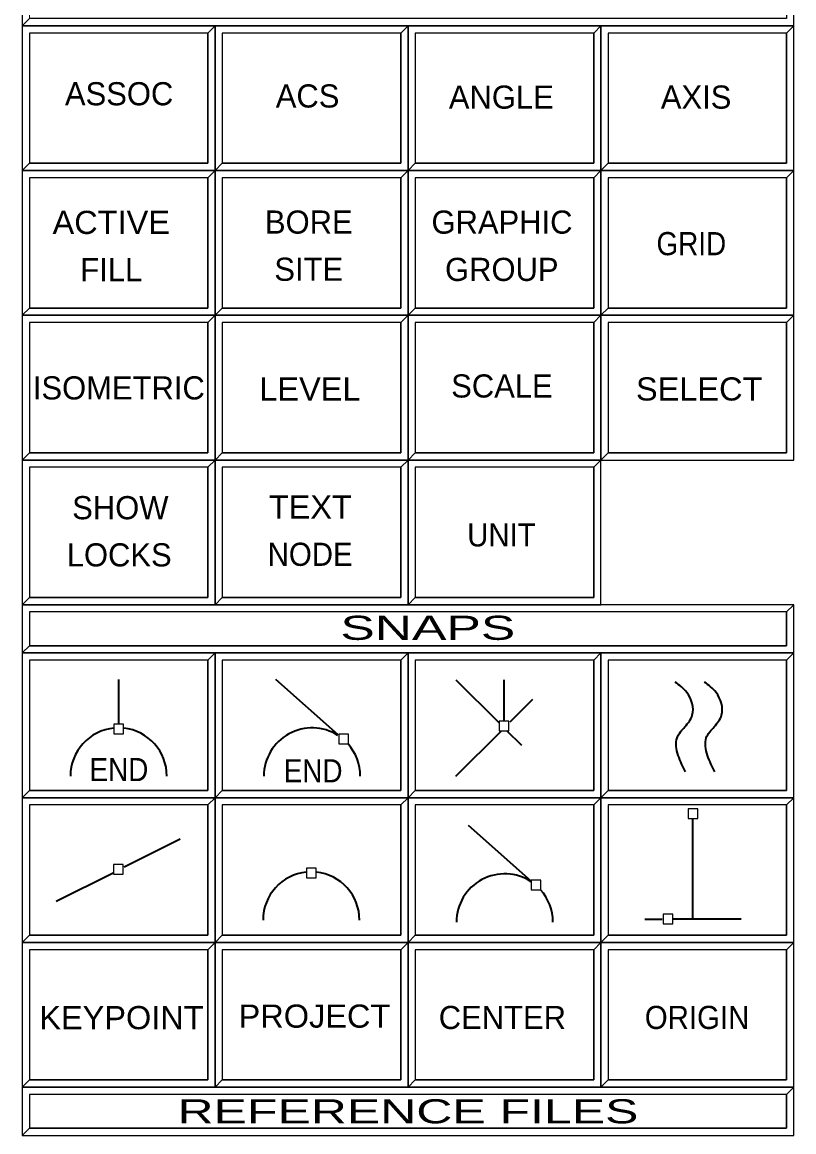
# Model space of a CAD drawing. Extents: x 95906.8 to 95923.6, y 90964.8 to 90972.8.
# Drawn here: x 95916.332 to 95917.932, y 90967.969 to 90970.269 of the extents above; entities that cross this region are included whole.
import ezdxf
from ezdxf.enums import TextEntityAlignment as Align

# ---------------------------------------------------------------- set-up
doc = ezdxf.new("R2010")
doc.units = 0
doc.header["$LTSCALE"] = 0.019
doc.linetypes.add('MEDIUM_DASHED', pattern=[4.5, 3, -1.5])
for name, color, linetype, lineweight in [('1', 7, 'Continuous', 25), ('11', 7, 'Continuous', 25), ('12', 7, 'Continuous', 25), ('2', 7, 'Continuous', 13), ('21', 7, 'Continuous', 25), ('3', 7, 'Continuous', 25), ('6', 7, 'Continuous', 35), ('7', 7, 'Continuous', 35)]:
    doc.layers.add(name, color=color, linetype=linetype, lineweight=lineweight)

msp = doc.modelspace()

# ---------------------------------------------------------------- linework, layer by layer
at = {"layer": '1'}
for points in [[(95916.3323, 90970.2617), (95917.9323, 90970.2617), (95917.9323, 90970.3617), (95916.3323, 90970.3617)], [(95916.3323, 90969.9617), (95916.7323, 90969.9617), (95916.7323, 90970.2617), (95916.3323, 90970.2617)], [(95916.7323, 90969.9617), (95917.1323, 90969.9617), (95917.1323, 90970.2617), (95916.7323, 90970.2617)], [(95917.1323, 90969.9617), (95917.5323, 90969.9617), (95917.5323, 90970.2617), (95917.1323, 90970.2617)], [(95917.5323, 90969.9617), (95917.9323, 90969.9617), (95917.9323, 90970.2617), (95917.5323, 90970.2617)], [(95916.3323, 90969.6617), (95916.7323, 90969.6617), (95916.7323, 90969.9617), (95916.3323, 90969.9617)], [(95916.7323, 90969.6617), (95917.1323, 90969.6617), (95917.1323, 90969.9617), (95916.7323, 90969.9617)], [(95917.1323, 90969.6617), (95917.5323, 90969.6617), (95917.5323, 90969.9617), (95917.1323, 90969.9617)], [(95917.5323, 90969.6617), (95917.9323, 90969.6617), (95917.9323, 90969.9617), (95917.5323, 90969.9617)], [(95916.3323, 90969.3617), (95916.7323, 90969.3617), (95916.7323, 90969.6617), (95916.3323, 90969.6617)], [(95916.7323, 90969.3617), (95917.1323, 90969.3617), (95917.1323, 90969.6617), (95916.7323, 90969.6617)], [(95917.1323, 90969.3617), (95917.5323, 90969.3617), (95917.5323, 90969.6617), (95917.1323, 90969.6617)], [(95917.5323, 90969.3617), (95917.9323, 90969.3617), (95917.9323, 90969.6617), (95917.5323, 90969.6617)], [(95916.3323, 90969.0617), (95916.7323, 90969.0617), (95916.7323, 90969.3617), (95916.3323, 90969.3617)], [(95916.7323, 90969.0617), (95917.1323, 90969.0617), (95917.1323, 90969.3617), (95916.7323, 90969.3617)], [(95917.1323, 90969.0617), (95917.5323, 90969.0617), (95917.5323, 90969.3617), (95917.1323, 90969.3617)], [(95916.3323, 90968.9617), (95917.9323, 90968.9617), (95917.9323, 90969.0617), (95916.3323, 90969.0617)], [(95916.3323, 90968.6617), (95916.7323, 90968.6617), (95916.7323, 90968.9617), (95916.3323, 90968.9617)], [(95916.7323, 90968.6617), (95917.1323, 90968.6617), (95917.1323, 90968.9617), (95916.7323, 90968.9617)], [(95917.1323, 90968.6617), (95917.5323, 90968.6617), (95917.5323, 90968.9617), (95917.1323, 90968.9617)], [(95917.5323, 90968.6617), (95917.9323, 90968.6617), (95917.9323, 90968.9617), (95917.5323, 90968.9617)], [(95916.3323, 90968.3617), (95916.7323, 90968.3617), (95916.7323, 90968.6617), (95916.3323, 90968.6617)], [(95916.7323, 90968.3617), (95917.1323, 90968.3617), (95917.1323, 90968.6617), (95916.7323, 90968.6617)], [(95917.1323, 90968.3617), (95917.5323, 90968.3617), (95917.5323, 90968.6617), (95917.1323, 90968.6617)], [(95917.5323, 90968.3617), (95917.9323, 90968.3617), (95917.9323, 90968.6617), (95917.5323, 90968.6617)], [(95916.3323, 90968.0617), (95916.7323, 90968.0617), (95916.7323, 90968.3617), (95916.3323, 90968.3617)], [(95916.7323, 90968.0617), (95917.1323, 90968.0617), (95917.1323, 90968.3617), (95916.7323, 90968.3617)], [(95917.1323, 90968.0617), (95917.5323, 90968.0617), (95917.5323, 90968.3617), (95917.1323, 90968.3617)], [(95917.5323, 90968.0617), (95917.9323, 90968.0617), (95917.9323, 90968.3617), (95917.5323, 90968.3617)], [(95916.3323, 90967.9617), (95917.9323, 90967.9617), (95917.9323, 90968.0617), (95916.3323, 90968.0617)]]:
    msp.add_lwpolyline(points, close=True, dxfattribs=at)
at = {"layer": '11'}
for points in [[(95916.3473, 90969.9767), (95916.7173, 90969.9767), (95916.7173, 90970.2467), (95916.3473, 90970.2467)], [(95916.7473, 90969.9767), (95917.1173, 90969.9767), (95917.1173, 90970.2467), (95916.7473, 90970.2467)], [(95917.1473, 90969.9767), (95917.5173, 90969.9767), (95917.5173, 90970.2467), (95917.1473, 90970.2467)], [(95916.3473, 90969.6767), (95916.7173, 90969.6767), (95916.7173, 90969.9467), (95916.3473, 90969.9467)], [(95916.7473, 90969.6767), (95917.1173, 90969.6767), (95917.1173, 90969.9467), (95916.7473, 90969.9467)], [(95917.1473, 90969.6767), (95917.5173, 90969.6767), (95917.5173, 90969.9467), (95917.1473, 90969.9467)], [(95917.5473, 90969.6767), (95917.9173, 90969.6767), (95917.9173, 90969.9467), (95917.5473, 90969.9467)], [(95916.3473, 90969.3767), (95916.7173, 90969.3767), (95916.7173, 90969.6467), (95916.3473, 90969.6467)], [(95916.7473, 90969.3767), (95917.1173, 90969.3767), (95917.1173, 90969.6467), (95916.7473, 90969.6467)], [(95917.1473, 90969.3767), (95917.5173, 90969.3767), (95917.5173, 90969.6467), (95917.1473, 90969.6467)], [(95917.5473, 90969.3767), (95917.9173, 90969.3767), (95917.9173, 90969.6467), (95917.5473, 90969.6467)], [(95916.3473, 90969.0767), (95916.7173, 90969.0767), (95916.7173, 90969.3467), (95916.3473, 90969.3467)], [(95916.7473, 90969.0767), (95917.1173, 90969.0767), (95917.1173, 90969.3467), (95916.7473, 90969.3467)], [(95917.1473, 90969.0767), (95917.5173, 90969.0767), (95917.5173, 90969.3467), (95917.1473, 90969.3467)], [(95916.7473, 90968.6767), (95917.1173, 90968.6767), (95917.1173, 90968.9467), (95916.7473, 90968.9467)], [(95917.1473, 90968.6767), (95917.5173, 90968.6767), (95917.5173, 90968.9467), (95917.1473, 90968.9467)], [(95917.5473, 90968.6767), (95917.9173, 90968.6767), (95917.9173, 90968.9467), (95917.5473, 90968.9467)], [(95916.3473, 90968.3767), (95916.7173, 90968.3767), (95916.7173, 90968.6467), (95916.3473, 90968.6467)], [(95916.7473, 90968.3767), (95917.1173, 90968.3767), (95917.1173, 90968.6467), (95916.7473, 90968.6467)], [(95917.1473, 90968.3767), (95917.5173, 90968.3767), (95917.5173, 90968.6467), (95917.1473, 90968.6467)], [(95917.5473, 90968.3767), (95917.9173, 90968.3767), (95917.9173, 90968.6467), (95917.5473, 90968.6467)], [(95916.3473, 90968.0767), (95916.7173, 90968.0767), (95916.7173, 90968.3467), (95916.3473, 90968.3467)], [(95916.7473, 90968.0767), (95917.1173, 90968.0767), (95917.1173, 90968.3467), (95916.7473, 90968.3467)], [(95917.1473, 90968.0767), (95917.5173, 90968.0767), (95917.5173, 90968.3467), (95917.1473, 90968.3467)], [(95917.5473, 90968.0767), (95917.9173, 90968.0767), (95917.9173, 90968.3467), (95917.5473, 90968.3467)]]:
    msp.add_lwpolyline(points, close=True, dxfattribs=at)
at = {"layer": '12'}
for points in [[(95917.5473, 90969.9767), (95917.9173, 90969.9767), (95917.9173, 90970.2467), (95917.5473, 90970.2467)], [(95916.3473, 90968.6767), (95916.7173, 90968.6767), (95916.7173, 90968.9467), (95916.3473, 90968.9467)]]:
    msp.add_lwpolyline(points, close=True, dxfattribs=at)
at = {"layer": '2'}
for points in [[(95916.3323, 90970.3617), (95916.3323, 90970.2617), (95916.3473, 90970.2767), (95916.3473, 90970.3467), (95917.9173, 90970.3467), (95917.9323, 90970.3617)], [(95916.3323, 90970.2617), (95916.3323, 90969.9617), (95916.3473, 90969.9767), (95916.3473, 90970.2467), (95916.7173, 90970.2467), (95916.7323, 90970.2617)], [(95916.7323, 90970.2617), (95916.7323, 90969.9617), (95916.7473, 90969.9767), (95916.7473, 90970.2467), (95917.1173, 90970.2467), (95917.1323, 90970.2617)], [(95917.1323, 90970.2617), (95917.1323, 90969.9617), (95917.1473, 90969.9767), (95917.1473, 90970.2467), (95917.5173, 90970.2467), (95917.5323, 90970.2617)], [(95917.5323, 90970.2617), (95917.5323, 90969.9617), (95917.5473, 90969.9767), (95917.5473, 90970.2467), (95917.9173, 90970.2467), (95917.9323, 90970.2617)], [(95916.3323, 90969.9617), (95916.3323, 90969.6617), (95916.3473, 90969.6767), (95916.3473, 90969.9467), (95916.7173, 90969.9467), (95916.7323, 90969.9617)], [(95916.7323, 90969.9617), (95916.7323, 90969.6617), (95916.7473, 90969.6767), (95916.7473, 90969.9467), (95917.1173, 90969.9467), (95917.1323, 90969.9617)], [(95917.1323, 90969.9617), (95917.1323, 90969.6617), (95917.1473, 90969.6767), (95917.1473, 90969.9467), (95917.5173, 90969.9467), (95917.5323, 90969.9617)], [(95917.5323, 90969.9617), (95917.5323, 90969.6617), (95917.5473, 90969.6767), (95917.5473, 90969.9467), (95917.9173, 90969.9467), (95917.9323, 90969.9617)], [(95916.3323, 90969.6617), (95916.3323, 90969.3617), (95916.3473, 90969.3767), (95916.3473, 90969.6467), (95916.7173, 90969.6467), (95916.7323, 90969.6617)], [(95916.7323, 90969.6617), (95916.7323, 90969.3617), (95916.7473, 90969.3767), (95916.7473, 90969.6467), (95917.1173, 90969.6467), (95917.1323, 90969.6617)], [(95917.1323, 90969.6617), (95917.1323, 90969.3617), (95917.1473, 90969.3767), (95917.1473, 90969.6467), (95917.5173, 90969.6467), (95917.5323, 90969.6617)], [(95917.5323, 90969.6617), (95917.5323, 90969.3617), (95917.5473, 90969.3767), (95917.5473, 90969.6467), (95917.9173, 90969.6467), (95917.9323, 90969.6617)], [(95916.3323, 90969.3617), (95916.3323, 90969.0617), (95916.3473, 90969.0767), (95916.3473, 90969.3467), (95916.7173, 90969.3467), (95916.7323, 90969.3617)], [(95916.7323, 90969.3617), (95916.7323, 90969.0617), (95916.7473, 90969.0767), (95916.7473, 90969.3467), (95917.1173, 90969.3467), (95917.1323, 90969.3617)], [(95917.1323, 90969.3617), (95917.1323, 90969.0617), (95917.1473, 90969.0767), (95917.1473, 90969.3467), (95917.5173, 90969.3467), (95917.5323, 90969.3617)], [(95916.3323, 90969.0617), (95916.3323, 90968.9617), (95916.3473, 90968.9767), (95916.3473, 90969.0467), (95917.9173, 90969.0467), (95917.9323, 90969.0617)], [(95916.3323, 90968.9617), (95916.3323, 90968.6617), (95916.3473, 90968.6767), (95916.3473, 90968.9467), (95916.7173, 90968.9467), (95916.7323, 90968.9617)], [(95916.7323, 90968.9617), (95916.7323, 90968.6617), (95916.7473, 90968.6767), (95916.7473, 90968.9467), (95917.1173, 90968.9467), (95917.1323, 90968.9617)], [(95917.1323, 90968.9617), (95917.1323, 90968.6617), (95917.1473, 90968.6767), (95917.1473, 90968.9467), (95917.5173, 90968.9467), (95917.5323, 90968.9617)], [(95917.5323, 90968.9617), (95917.5323, 90968.6617), (95917.5473, 90968.6767), (95917.5473, 90968.9467), (95917.9173, 90968.9467), (95917.9323, 90968.9617)], [(95916.3323, 90968.6617), (95916.3323, 90968.3617), (95916.3473, 90968.3767), (95916.3473, 90968.6467), (95916.7173, 90968.6467), (95916.7323, 90968.6617)], [(95916.7323, 90968.6617), (95916.7323, 90968.3617), (95916.7473, 90968.3767), (95916.7473, 90968.6467), (95917.1173, 90968.6467), (95917.1323, 90968.6617)], [(95917.1323, 90968.6617), (95917.1323, 90968.3617), (95917.1473, 90968.3767), (95917.1473, 90968.6467), (95917.5173, 90968.6467), (95917.5323, 90968.6617)], [(95917.5323, 90968.6617), (95917.5323, 90968.3617), (95917.5473, 90968.3767), (95917.5473, 90968.6467), (95917.9173, 90968.6467), (95917.9323, 90968.6617)], [(95916.3323, 90968.3617), (95916.3323, 90968.0617), (95916.3473, 90968.0767), (95916.3473, 90968.3467), (95916.7173, 90968.3467), (95916.7323, 90968.3617)], [(95916.7323, 90968.3617), (95916.7323, 90968.0617), (95916.7473, 90968.0767), (95916.7473, 90968.3467), (95917.1173, 90968.3467), (95917.1323, 90968.3617)], [(95917.1323, 90968.3617), (95917.1323, 90968.0617), (95917.1473, 90968.0767), (95917.1473, 90968.3467), (95917.5173, 90968.3467), (95917.5323, 90968.3617)], [(95917.5323, 90968.3617), (95917.5323, 90968.0617), (95917.5473, 90968.0767), (95917.5473, 90968.3467), (95917.9173, 90968.3467), (95917.9323, 90968.3617)], [(95916.3323, 90968.0617), (95916.3323, 90967.9617), (95916.3473, 90967.9767), (95916.3473, 90968.0467), (95917.9173, 90968.0467), (95917.9323, 90968.0617)]]:
    msp.add_lwpolyline(points, close=True, dxfattribs=at)
at = {"layer": '21'}
for points in [[(95916.3473, 90968.9767), (95917.9173, 90968.9767), (95917.9173, 90969.0467), (95916.3473, 90969.0467)], [(95916.3473, 90967.9767), (95917.9173, 90967.9767), (95917.9173, 90968.0467), (95916.3473, 90968.0467)]]:
    msp.add_lwpolyline(points, close=True, dxfattribs=at)
at = {"layer": '3'}
for points in [[(95916.3323, 90970.2617), (95917.9323, 90970.2617), (95917.9323, 90970.3617), (95917.9173, 90970.3467), (95917.9173, 90970.2767), (95916.3473, 90970.2767)], [(95916.3323, 90969.9617), (95916.7323, 90969.9617), (95916.7323, 90970.2617), (95916.7173, 90970.2467), (95916.7173, 90969.9767), (95916.3473, 90969.9767)], [(95916.7323, 90969.9617), (95917.1323, 90969.9617), (95917.1323, 90970.2617), (95917.1173, 90970.2467), (95917.1173, 90969.9767), (95916.7473, 90969.9767)], [(95917.1323, 90969.9617), (95917.5323, 90969.9617), (95917.5323, 90970.2617), (95917.5173, 90970.2467), (95917.5173, 90969.9767), (95917.1473, 90969.9767)], [(95917.5323, 90969.9617), (95917.9323, 90969.9617), (95917.9323, 90970.2617), (95917.9173, 90970.2467), (95917.9173, 90969.9767), (95917.5473, 90969.9767)], [(95916.3323, 90969.6617), (95916.7323, 90969.6617), (95916.7323, 90969.9617), (95916.7173, 90969.9467), (95916.7173, 90969.6767), (95916.3473, 90969.6767)], [(95916.7323, 90969.6617), (95917.1323, 90969.6617), (95917.1323, 90969.9617), (95917.1173, 90969.9467), (95917.1173, 90969.6767), (95916.7473, 90969.6767)], [(95917.1323, 90969.6617), (95917.5323, 90969.6617), (95917.5323, 90969.9617), (95917.5173, 90969.9467), (95917.5173, 90969.6767), (95917.1473, 90969.6767)], [(95917.5323, 90969.6617), (95917.9323, 90969.6617), (95917.9323, 90969.9617), (95917.9173, 90969.9467), (95917.9173, 90969.6767), (95917.5473, 90969.6767)], [(95916.3323, 90969.3617), (95916.7323, 90969.3617), (95916.7323, 90969.6617), (95916.7173, 90969.6467), (95916.7173, 90969.3767), (95916.3473, 90969.3767)], [(95916.7323, 90969.3617), (95917.1323, 90969.3617), (95917.1323, 90969.6617), (95917.1173, 90969.6467), (95917.1173, 90969.3767), (95916.7473, 90969.3767)], [(95917.1323, 90969.3617), (95917.5323, 90969.3617), (95917.5323, 90969.6617), (95917.5173, 90969.6467), (95917.5173, 90969.3767), (95917.1473, 90969.3767)], [(95917.5323, 90969.3617), (95917.9323, 90969.3617), (95917.9323, 90969.6617), (95917.9173, 90969.6467), (95917.9173, 90969.3767), (95917.5473, 90969.3767)], [(95916.3323, 90969.0617), (95916.7323, 90969.0617), (95916.7323, 90969.3617), (95916.7173, 90969.3467), (95916.7173, 90969.0767), (95916.3473, 90969.0767)], [(95916.7323, 90969.0617), (95917.1323, 90969.0617), (95917.1323, 90969.3617), (95917.1173, 90969.3467), (95917.1173, 90969.0767), (95916.7473, 90969.0767)], [(95917.1323, 90969.0617), (95917.5323, 90969.0617), (95917.5323, 90969.3617), (95917.5173, 90969.3467), (95917.5173, 90969.0767), (95917.1473, 90969.0767)], [(95916.3323, 90968.9617), (95917.9323, 90968.9617), (95917.9323, 90969.0617), (95917.9173, 90969.0467), (95917.9173, 90968.9767), (95916.3473, 90968.9767)], [(95916.3323, 90968.6617), (95916.7323, 90968.6617), (95916.7323, 90968.9617), (95916.7173, 90968.9467), (95916.7173, 90968.6767), (95916.3473, 90968.6767)], [(95916.7323, 90968.6617), (95917.1323, 90968.6617), (95917.1323, 90968.9617), (95917.1173, 90968.9467), (95917.1173, 90968.6767), (95916.7473, 90968.6767)], [(95917.1323, 90968.6617), (95917.5323, 90968.6617), (95917.5323, 90968.9617), (95917.5173, 90968.9467), (95917.5173, 90968.6767), (95917.1473, 90968.6767)], [(95917.5323, 90968.6617), (95917.9323, 90968.6617), (95917.9323, 90968.9617), (95917.9173, 90968.9467), (95917.9173, 90968.6767), (95917.5473, 90968.6767)], [(95916.3323, 90968.3617), (95916.7323, 90968.3617), (95916.7323, 90968.6617), (95916.7173, 90968.6467), (95916.7173, 90968.3767), (95916.3473, 90968.3767)], [(95916.7323, 90968.3617), (95917.1323, 90968.3617), (95917.1323, 90968.6617), (95917.1173, 90968.6467), (95917.1173, 90968.3767), (95916.7473, 90968.3767)], [(95917.1323, 90968.3617), (95917.5323, 90968.3617), (95917.5323, 90968.6617), (95917.5173, 90968.6467), (95917.5173, 90968.3767), (95917.1473, 90968.3767)], [(95917.5323, 90968.3617), (95917.9323, 90968.3617), (95917.9323, 90968.6617), (95917.9173, 90968.6467), (95917.9173, 90968.3767), (95917.5473, 90968.3767)], [(95916.3323, 90968.0617), (95916.7323, 90968.0617), (95916.7323, 90968.3617), (95916.7173, 90968.3467), (95916.7173, 90968.0767), (95916.3473, 90968.0767)], [(95916.7323, 90968.0617), (95917.1323, 90968.0617), (95917.1323, 90968.3617), (95917.1173, 90968.3467), (95917.1173, 90968.0767), (95916.7473, 90968.0767)], [(95917.1323, 90968.0617), (95917.5323, 90968.0617), (95917.5323, 90968.3617), (95917.5173, 90968.3467), (95917.5173, 90968.0767), (95917.1473, 90968.0767)], [(95917.5323, 90968.0617), (95917.9323, 90968.0617), (95917.9323, 90968.3617), (95917.9173, 90968.3467), (95917.9173, 90968.0767), (95917.5473, 90968.0767)], [(95916.3323, 90967.9617), (95917.9323, 90967.9617), (95917.9323, 90968.0617), (95917.9173, 90968.0467), (95917.9173, 90967.9767), (95916.3473, 90967.9767)]]:
    msp.add_lwpolyline(points, close=True, dxfattribs=at)
at = {"layer": '6'}
for p, q in [((95916.5323, 90968.9064), (95916.5323, 90968.814)), ((95916.9875, 90968.7918), (95916.8584, 90968.9064)), ((95917.2316, 90968.9063), (95917.3204, 90968.8175)), ((95917.3316, 90968.8205), (95917.3316, 90968.9063)), ((95917.2316, 90968.7063), (95917.3252, 90968.7999)), ((95917.7231, 90968.4099), (95917.7231, 90968.6184)), ((95917.3879, 90968.4885), (95917.2578, 90968.6039)), ((95916.6596, 90968.5756), (95916.5441, 90968.5178)), ((95916.4027, 90968.4471), (95916.5207, 90968.506)), ((95917.6231, 90968.4099), (95917.6595, 90968.4099)), ((95917.8231, 90968.4099), (95917.6814, 90968.4099))]:
    msp.add_line(p, q, dxfattribs=at)
at = {"layer": '6', "linetype": 'MEDIUM_DASHED'}
for p, q in [((95917.3908, 90968.8655), (95917.3436, 90968.8183)), ((95917.3682, 90968.7696), (95917.3374, 90968.8003))]:
    msp.add_line(p, q, dxfattribs=at)
at = {"layer": '6', "lineweight": 25}
for points in [[(95917.3213, 90968.8005), (95917.3413, 90968.8005), (95917.3413, 90968.8205), (95917.3213, 90968.8205)], [(95916.5223, 90968.794), (95916.5423, 90968.794), (95916.5423, 90968.814), (95916.5223, 90968.814)], [(95916.9886, 90968.7731), (95917.0086, 90968.7731), (95917.0086, 90968.7931), (95916.9886, 90968.7931)], [(95917.7131, 90968.6184), (95917.7331, 90968.6184), (95917.7331, 90968.6384), (95917.7131, 90968.6384)], [(95916.5217, 90968.5034), (95916.5417, 90968.5034), (95916.5417, 90968.5234), (95916.5217, 90968.5234)], [(95916.9218, 90968.4957), (95916.9418, 90968.4957), (95916.9418, 90968.5157), (95916.9218, 90968.5157)], [(95917.388, 90968.4706), (95917.408, 90968.4706), (95917.408, 90968.4906), (95917.388, 90968.4906)], [(95917.6614, 90968.4001), (95917.6814, 90968.4001), (95917.6814, 90968.4201), (95917.6614, 90968.4201)]]:
    msp.add_lwpolyline(points, close=True, dxfattribs=at)
at = {"layer": '6'}
for centre, start, end in [((95916.5323, 90968.7064), 95.4769, 180), ((95916.5323, 90968.7064), 0, 83.8749), ((95916.9334, 90968.7064), 57.6387, 180), ((95916.9334, 90968.7064), 0, 41.8322), ((95916.9318, 90968.4081), 95.6733, 180), ((95916.9318, 90968.4081), 95.3189, 95.3388), ((95916.9318, 90968.4081), 0, 83.9551), ((95917.3328, 90968.4039), 56.474, 180), ((95917.3328, 90968.4039), 0, 41.9755)]:
    msp.add_arc(centre, 0.1, start, end, dxfattribs=at)
for points in [[(95917.7079, 90968.7153), (95917.6927, 90968.7495), (95917.6902, 90968.7861), (95917.7066, 90968.8089), (95917.7218, 90968.8329), (95917.7104, 90968.8798), (95917.6863, 90968.9012)], [(95917.7686, 90968.7153), (95917.7534, 90968.7495), (95917.7509, 90968.7861), (95917.7673, 90968.8089), (95917.7825, 90968.8329), (95917.7711, 90968.8798), (95917.7471, 90968.9012)]]:
    msp.add_spline(points, degree=3, dxfattribs=at)

# ---------------------------------------------------------------- texts
at = {"layer": '21', "width": 1.55}
msp.add_text('    REFERENCE FILES    ', height=0.04999, dxfattribs=at).set_placement((95917.1322, 90967.9867), align=Align.CENTER)
at = {"layer": '6'}
for s, p in [('ASSOC', (95916.5333, 90970.0969)), ('ACS', (95916.9241, 90970.0923)), ('ANGLE', (95917.3258, 90970.0899)), ('AXIS', (95917.7297, 90970.09)), ('BORE', (95916.9266, 90969.8309)), ('GRAPHIC', (95917.3272, 90969.8308)), ('FILL', (95916.517, 90969.7324)), ('SITE', (95916.9265, 90969.7331)), ('GROUP', (95917.3268, 90969.7328)), ('ISOMETRIC', (95916.5327, 90969.4872)), ('SCALE', (95917.3271, 90969.4912)), ('SHOW', (95916.5358, 90969.2389)), ('LOCKS', (95916.5335, 90969.1411)), ('CENTER', (95917.328, 90968.1822))]:
    msp.add_text(s, height=0.048, dxfattribs=at).set_placement(p, align=Align.CENTER)
for s, width, p in [('ACTIVE', 1.05, (95916.517, 90969.8302)), ('GRID', 0.9, (95917.7198, 90969.7862)), ('LEVEL', 1.05, (95916.929, 90969.4849)), ('SELECT', 1.05, (95917.7361, 90969.485)), ('TEXT', 1.05, (95916.9298, 90969.2403)), ('UNIT', 0.95, (95917.3261, 90969.1825)), ('NODE', 0.95, (95916.9294, 90969.1423)), ('END', 0.9, (95916.5329, 90968.6961)), ('END', 0.9, (95916.9356, 90968.6935)), ('KEYPOINT', 1.05, (95916.5381, 90968.1819)), ('PROJECT', 1.05, (95916.9383, 90968.185)), ('ORIGIN', 0.95, (95917.7317, 90968.1823))]:
    msp.add_text(s, height=0.048, dxfattribs=dict(at, width=width)).set_placement(p, align=Align.CENTER)
at = {"layer": '7', "width": 1.6}
msp.add_text('         SNAPS         ', height=0.05, dxfattribs=at).set_placement((95917.1734, 90968.9889), align=Align.CENTER)

doc.saveas('drawing.dxf')
